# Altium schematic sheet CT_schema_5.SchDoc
size 176 x 147 mm
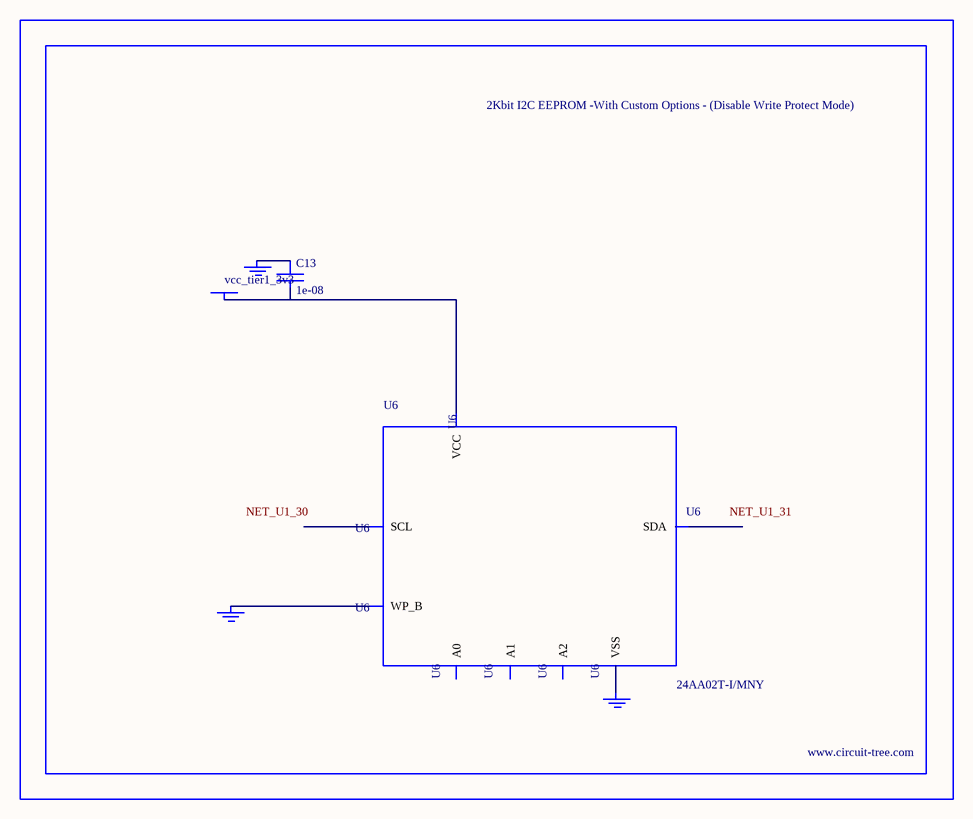
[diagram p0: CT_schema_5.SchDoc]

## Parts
BORDER4  (no value)
C13  1e-08  [C0402]
GND_INSTANCE_4_0  (no value)
GND_INSTANCE_4_1  (no value)
GND_INSTANCE_4_2  (no value)
POWER_INSTANCE_4_0  vcc_tier1_3v3
U6  24AA02T-I/MNY  [TDFN-8/6MM]

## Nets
NetC13_1: C13.1 GND_INSTANCE_4_1.0(GND)
NetC13_2: C13.2 POWER_INSTANCE_4_0.0(PWR) U6.8(VCC)
NetGND_INSTANCE_4_0_0: GND_INSTANCE_4_0.0(GND) U6.7(WP_B)
NetGND_INSTANCE_4_2_0: GND_INSTANCE_4_2.0(GND) U6.4(VSS)

Not connected (* = marked no-connect by the designer): U6 1(A0) 2(A1) 3(A2) 5(SDA) 6(SCL)

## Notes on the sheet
- Labels drawn without touching a wire or pin: NET_U1_30, NET_U1_31

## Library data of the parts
BORDER4 = BORDER_PAGE4
C13 = C0402C103K3RAC
GND_INSTANCE_4_0-GND_INSTANCE_4_2 = GND
POWER_INSTANCE_4_0 = PWR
